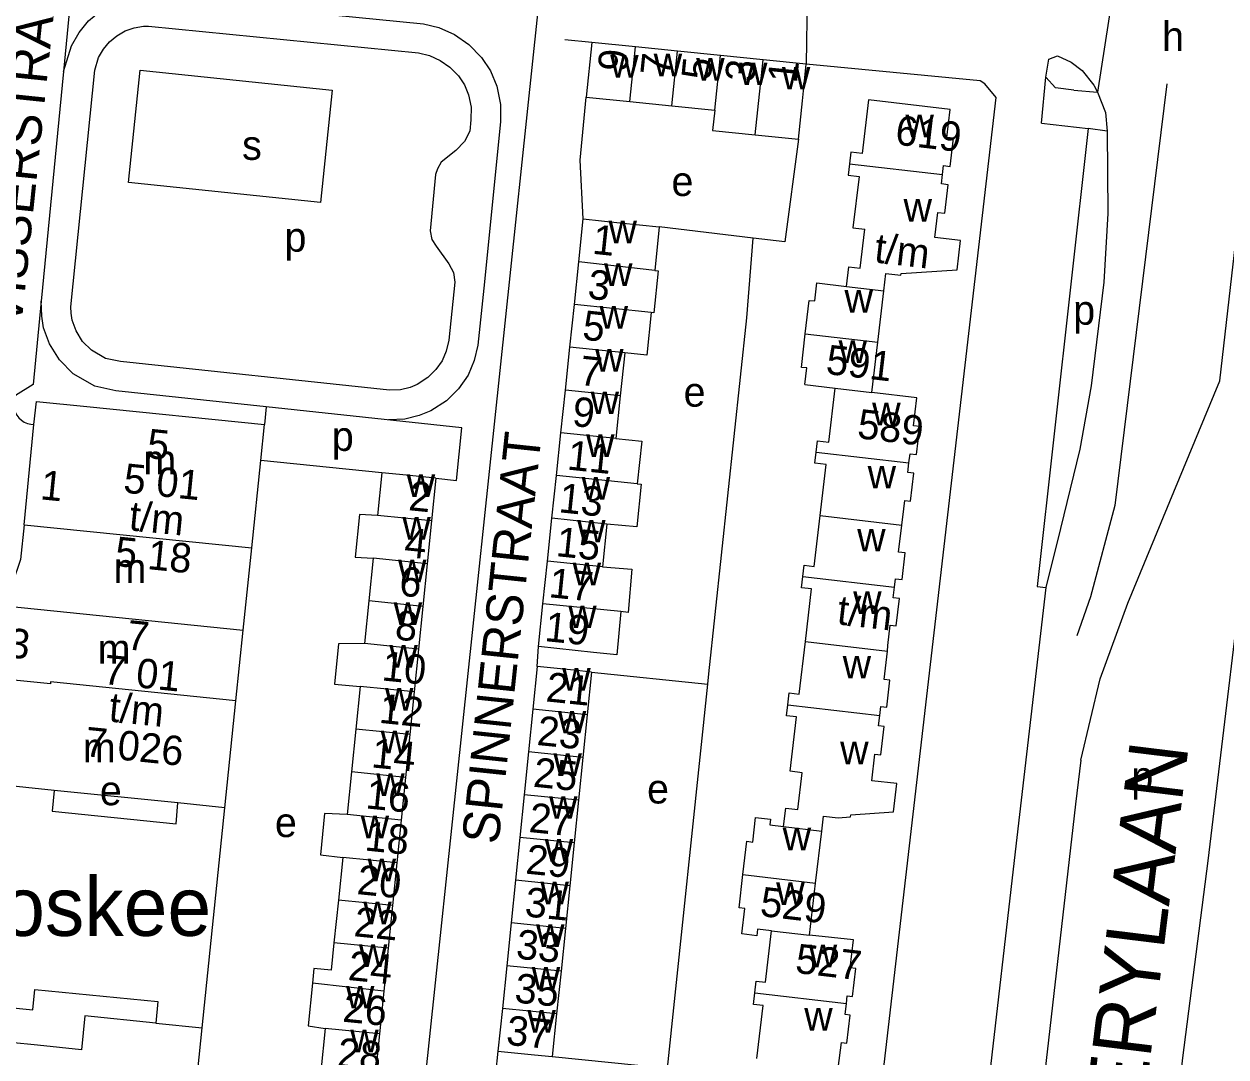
# Model space of a CAD drawing. Extents: x 159902 to 161769, y 383692 to 384875.
# Drawn here: x 161124 to 161287.3, y 384531.5 to 384671.8 of the extents above; entities that cross this region are included whole.
import ezdxf

# ---------------------------------------------------------------- set-up
doc = ezdxf.new("R2010")
doc.units = 0
for name, color, linetype in [('BLT_Basislijn', 7, 'Continuous'), ('BLT_Bebouwing', 7, 'Continuous'), ('BLT_Bebouwing_beschrifting', 7, 'Continuous'), ('BLT_Centroide', 7, 'Continuous'), ('BLT_Huisnummer', 7, 'Continuous'), ('BLT_Huisnummer_ tussenligend', 7, 'Continuous'), ('BLT_Huisnummer_reeks', 7, 'Continuous'), ('BLT_Onderverdeling_panden', 7, 'Continuous'), ('BLT_Straatnaam', 7, 'Continuous'), ('BLT_Straatnaam_hoofdweg', 7, 'Continuous'), ('BLT_Vlakafsluiter', 7, 'Continuous')]:
    doc.layers.add(name, color=color, linetype=linetype)

msp = doc.modelspace()

# ---------------------------------------------------------------- linework, layer by layer
at = {"layer": 'BLT_Basislijn'}
for p, q in [((161193.76, 384673.22), (161175.44, 384500)), ((161201.12, 384669.34), (161197.44, 384669.67)), ((161262.19, 384658.36), (161262.82, 384664.61)), ((161279.25, 384663.69), (161272.18, 384606.45)), ((161266.61, 384662.85), (161269.82, 384662.59)), ((161262.19, 384658.36), (161268.57, 384657.64)), ((161223.05, 384642.76), (161210.28, 384644.28)), ((161291.56, 384614.73), (161284.82, 384558.18)), ((161172.6, 384610.88), (161156.15, 384612.55)), ((161262.8, 384595.29), (161258.48, 384558.22)), ((161268.88, 384594.05), (161266.99, 384588.75)), ((161193.71, 384584.56), (161193.89, 384587.27)), ((161201.08, 384583.81), (161216.88, 384582.19)), ((161211.42, 384530.02), (161216.88, 384582.19)), ((161267.56, 384571.85), (161266.85, 384565.87)), ((161266.85, 384565.87), (161261.55, 384519.94)), ((161258.48, 384558.22), (161254.02, 384519.21)), ((161188.38, 384532.33), (161188.05, 384529.26)), ((161195.75, 384531.58), (161211.42, 384530.02))]:
    msp.add_line(p, q, dxfattribs=at)
for points in [[(161128.1, 384675.7), (161130.08, 384672.9), (161129.35, 384665.36)], [(161129.35, 384665.36), (161130.44, 384668.87), (161131.47, 384670.69), (161132.76, 384672.24), (161134.31, 384673.54), (161136.06, 384674.54), (161137.96, 384675.21), (161139.86, 384675.52), (161141.03, 384675.55), (161178.24, 384671.86), (161180.36, 384671.34), (161182.49, 384670.39), (161184.43, 384669.05), (161186.15, 384667.3), (161187.37, 384665.46), (161188.22, 384663.37), (161188.74, 384660.91), (161188.71, 384658.61), (161186.53, 384636.82)], [(161262.82, 384664.61), (161263.2, 384667.05), (161264.4, 384667.53), (161266.22, 384666.66), (161267.73, 384665.52), (161269.33, 384663.54), (161269.82, 384662.59)], [(161129.35, 384665.36), (161126.33, 384634.17)], [(161139.77, 384665.57), (161165.87, 384662.86), (161164.28, 384647.58), (161138.18, 384650.3), (161139.77, 384665.57)], [(161237.71, 384503.53), (161256.05, 384661.86), (161254.51, 384663.72), (161253.87, 384664.1), (161230.24, 384666.36)], [(161266.61, 384662.85), (161264.13, 384663.16), (161262.82, 384664.61)], [(161199.97, 384645.36), (161199.53, 384653.33), (161200.36, 384661.9)], [(161269.82, 384662.59), (161270.9, 384659.82), (161271.13, 384657.29)], [(161268.57, 384657.64), (161261.64, 384595.42), (161262.8, 384595.29)], [(161271.13, 384657.29), (161268.57, 384657.64)], [(161271.13, 384657.29), (161271.24, 384646.08), (161270.7, 384636.78), (161268.97, 384622.67)], [(161229.19, 384656.17), (161227.36, 384642.26), (161223.05, 384642.76)], [(161267.56, 384571.85), (161270.19, 384582.9), (161273.95, 384593.17), (161280.19, 384608.27), (161286.43, 384623.37), (161290.01, 384654.67)], [(161216.88, 384582.19), (161217.02, 384583.58), (161222.17, 384631.94), (161223.05, 384642.76)], [(161186.53, 384636.82), (161185.65, 384628.21), (161185.16, 384626.15), (161184.32, 384624.15), (161183.03, 384622.3), (161181.38, 384620.67), (161179.26, 384619.31), (161177.67, 384618.66), (161175.71, 384618.18), (161173.5, 384618.07)], [(161126.33, 384634.17), (161125.24, 384622.87), (161122.85, 384621.39)], [(161156.91, 384619.84), (161136.45, 384622.03), (161133.61, 384622.64), (161130.68, 384624.32), (161128.8, 384626.22), (161127.44, 384628.41), (161126.66, 384630.58), (161126.4, 384632.17), (161126.33, 384634.17)], [(161268.97, 384622.67), (161267.43, 384614.08), (161264.77, 384603.29), (161262.8, 384595.29)], [(161122.85, 384621.39), (161122.68, 384620.95), (161122.59, 384620.49), (161122.58, 384620.03), (161122.64, 384619.56), (161122.79, 384619.11), (161123.01, 384618.7), (161123.29, 384618.33), (161123.64, 384618.01), (161124.03, 384617.75), (161124.46, 384617.57), (161124.92, 384617.46), (161125.35, 384617.42)], [(161156.91, 384619.84), (161156.65, 384617.45)], [(161183.48, 384617), (161156.91, 384619.84)], [(161179.95, 384610.13), (161182.76, 384609.85), (161183.48, 384617)], [(161272.18, 384606.45), (161268.88, 384594.05)], [(161284.82, 384558.18), (161281.35, 384531.41), (161279.58, 384515.63)]]:
    msp.add_lwpolyline(points, dxfattribs=at)
msp.add_lwpolyline([(161140.89, 384671.55), (161177.56, 384667.91), (161179.06, 384667.54), (161180.52, 384666.89), (161181.84, 384665.97), (161183.02, 384664.77), (161183.82, 384663.57), (161184.39, 384662.19), (161184.73, 384660.52), (161184.71, 384658.82), (161184.57, 384657.26), (161183.85, 384655.87), (161182.65, 384654.65), (161180.67, 384653.05), (161180.14, 384652.18), (161179.89, 384651.38), (161179.17, 384643.72), (161179.4, 384642.56), (161179.99, 384641.64), (161181.72, 384639.24), (161182.32, 384638.08), (161182.51, 384636.75), (161181.69, 384628.87), (161181.35, 384627.4), (161180.8, 384626.1), (161179.95, 384624.89), (161178.86, 384623.81), (161177.41, 384622.87), (161176.43, 384622.48), (161175.12, 384622.15), (161173.62, 384622.08), (161137.09, 384625.99), (161135.06, 384626.42), (161133.14, 384627.52), (161131.96, 384628.71), (161131.07, 384630.15), (161130.55, 384631.6), (161130.39, 384632.57), (161130.36, 384633.4), (161133.6, 384665.55), (161134.13, 384667.28), (161134.77, 384668.41), (161135.61, 384669.41), (161136.6, 384670.24), (161137.73, 384670.89), (161138.96, 384671.32), (161140.24, 384671.53)], close=True, dxfattribs=at)
at = {"layer": 'BLT_Bebouwing'}
for p, q in [((161201.12, 384669.34), (161200.36, 384661.9)), ((161207.06, 384668.74), (161201.12, 384669.34)), ((161212.77, 384668.15), (161207.06, 384668.74)), ((161218.59, 384667.55), (161212.77, 384668.15)), ((161224.41, 384666.96), (161218.59, 384667.55)), ((161230.24, 384666.36), (161224.41, 384666.96)), ((161206.29, 384661.29), (161212.01, 384660.71)), ((161212.01, 384660.71), (161217.83, 384660.11)), ((161223.3, 384656.77), (161229.19, 384656.17)), ((161199.36, 384639.55), (161199.97, 384645.36)), ((161210.28, 384644.28), (161209.67, 384638.37)), ((161236.6, 384644.15), (161238.19, 384643.96)), ((161198.76, 384633.75), (161199.36, 384639.55)), ((161239.96, 384628.6), (161240.78, 384635.6)), ((161198.15, 384627.94), (161198.76, 384633.75)), ((161197.54, 384622.12), (161198.15, 384627.94)), ((161239.17, 384621.79), (161239.96, 384628.6)), ((161205.6, 384627.15), (161204.99, 384621.34)), ((161230.06, 384622.86), (161234.17, 384622.38)), ((161196.93, 384616.32), (161197.54, 384622.12)), ((161204.99, 384621.34), (161204.38, 384615.53)), ((161156.15, 384612.55), (161156.65, 384617.45)), ((161196.32, 384610.51), (161196.93, 384616.32)), ((161154.93, 384600.69), (161156.15, 384612.55)), ((161172.6, 384610.88), (161172.01, 384605.08)), ((161179.95, 384610.13), (161179.36, 384604.34)), ((161195.71, 384604.7), (161196.32, 384610.51)), ((161179.36, 384604.34), (161178.77, 384598.53)), ((161195.1, 384598.89), (161195.71, 384604.7)), ((161203.17, 384603.91), (161202.56, 384598.1)), ((161153.77, 384589.52), (161154.93, 384600.69)), ((161171.42, 384599.28), (161170.83, 384593.47)), ((161178.77, 384598.53), (161178.18, 384592.73)), ((161194.49, 384593.08), (161195.1, 384598.89)), ((161170.83, 384593.47), (161170.24, 384587.67)), ((161193.89, 384587.27), (161194.49, 384593.08)), ((161178.18, 384592.73), (161177.59, 384586.92)), ((161152.78, 384579.92), (161153.77, 384589.52)), ((161177.59, 384586.92), (161177, 384581.11)), ((161193.71, 384584.56), (161193.12, 384578.76)), ((161201.08, 384583.81), (161200.49, 384578.01)), ((161169.65, 384581.86), (161169.06, 384576.06)), ((161151.28, 384565.39), (161152.78, 384579.92)), ((161177, 384581.11), (161176.41, 384575.31)), ((161193.12, 384578.76), (161192.53, 384572.96)), ((161200.49, 384578.01), (161199.9, 384572.2)), ((161169.06, 384576.06), (161168.46, 384570.25)), ((161176.41, 384575.31), (161175.82, 384569.51)), ((161192.53, 384572.96), (161191.93, 384567.15)), ((161199.9, 384572.2), (161199.31, 384566.4)), ((161168.46, 384570.25), (161167.88, 384564.45)), ((161175.82, 384569.51), (161175.23, 384563.7)), ((161144.88, 384566.03), (161128.1, 384567.73)), ((161191.93, 384567.15), (161191.34, 384561.35)), ((161148.19, 384535.5), (161151.28, 384565.39)), ((161199.31, 384566.4), (161198.71, 384560.6)), ((161175.23, 384563.7), (161174.64, 384557.9)), ((161231.53, 384555.14), (161232.36, 384562.21)), ((161191.34, 384561.35), (161190.75, 384555.54)), ((161198.71, 384560.6), (161198.12, 384554.79)), ((161167.29, 384558.64), (161166.7, 384552.84)), ((161174.64, 384557.9), (161174.05, 384552.09)), ((161190.75, 384555.54), (161190.16, 384549.74)), ((161198.12, 384554.79), (161197.53, 384548.99)), ((161230.7, 384548.06), (161231.53, 384555.14)), ((161166.7, 384552.84), (161166.1, 384547.03)), ((161174.05, 384552.09), (161173.46, 384546.29)), ((161190.16, 384549.74), (161189.57, 384543.93)), ((161197.53, 384548.99), (161196.94, 384543.18)), ((161173.46, 384546.29), (161172.87, 384540.48)), ((161189.57, 384543.93), (161188.97, 384538.13)), ((161196.94, 384543.18), (161196.35, 384537.38)), ((161172.87, 384540.48), (161172.28, 384534.68)), ((161188.97, 384538.13), (161188.38, 384532.33)), ((161196.35, 384537.38), (161195.75, 384531.58)), ((161147.6, 384529.75), (161148.19, 384535.5)), ((161172.28, 384534.68), (161171.69, 384528.87))]:
    msp.add_line(p, q, dxfattribs=at)
for points in [[(161229.19, 384656.17), (161229.73, 384661.39), (161230.24, 384666.36)], [(161200.36, 384661.9), (161206.29, 384661.29)], [(161248.76, 384651.38), (161248.91, 384652.61), (161249.81, 384652.5), (161250.26, 384656.33), (161249.36, 384656.43), (161249.81, 384660.21), (161238.69, 384661.51), (161237.84, 384654.23), (161236.29, 384654.41), (161236.11, 384652.86)], [(161217.83, 384660.11), (161217.52, 384657.36), (161223.3, 384656.77)], [(161236.11, 384652.86), (161235.93, 384651.32), (161237.42, 384651.14), (161236.6, 384644.15)], [(161247.74, 384642.84), (161248.14, 384646.23), (161249.08, 384646.12), (161249.53, 384650.01), (161248.61, 384650.11), (161248.76, 384651.38)], [(161199.97, 384645.36), (161204.94, 384644.84), (161210.28, 384644.28)], [(161235.71, 384636.2), (161236.03, 384638.85), (161237.57, 384638.67), (161238.19, 384643.96)], [(161240.78, 384635.6), (161241.06, 384637.95), (161243.11, 384637.71), (161243.14, 384637.94), (161250.75, 384638.43), (161251.22, 384642.43), (161247.74, 384642.84)], [(161209.67, 384638.37), (161210.15, 384638.32), (161209.55, 384632.62), (161209.2, 384632.65)], [(161230.12, 384629.75), (161230.65, 384634.3), (161231.41, 384634.22), (161231.69, 384636.67), (161235.71, 384636.2)], [(161209.2, 384632.65), (161208.6, 384626.85), (161205.6, 384627.15)], [(161230.06, 384622.86), (161230.33, 384625.11), (161229.59, 384625.19), (161230.12, 384629.75)], [(161231.59, 384613.7), (161231.77, 384615.22), (161233.31, 384615.04), (161234.17, 384622.38)], [(161244.2, 384612.22), (161244.35, 384613.45), (161245.24, 384613.35), (161245.69, 384617.15), (161244.84, 384617.24), (161245.28, 384621.08), (161239.17, 384621.79)], [(161125.35, 384617.42), (161125.67, 384620.57)], [(161125.67, 384620.57), (161132.51, 384619.88), (161156.65, 384617.45)], [(161124, 384603.81), (161125.35, 384617.42)], [(161204.38, 384615.53), (161207.9, 384615.16), (161207.29, 384609.38)], [(161232.14, 384605.08), (161232.95, 384612), (161231.42, 384612.18), (161231.59, 384613.7)], [(161179.95, 384610.13), (161174.98, 384610.64), (161172.6, 384610.88)], [(161243.23, 384603.78), (161243.5, 384606), (161243.63, 384607.12), (161244.42, 384607.03), (161244.86, 384610.83), (161244.05, 384610.92), (161244.2, 384612.22)], [(161207.29, 384609.38), (161207.83, 384609.32), (161207.22, 384603.54), (161203.17, 384603.91)], [(161172.01, 384605.08), (161169.56, 384605.22), (161168.97, 384599.43), (161171.42, 384599.28)], [(161229.79, 384596.78), (161229.97, 384598.32), (161231.33, 384598.16), (161232.14, 384605.08)], [(161124, 384603.81), (161123.53, 384599.12), (161121.37, 384592.82)], [(161242.24, 384595.32), (161242.38, 384596.47), (161243.27, 384596.37), (161243.7, 384600), (161242.78, 384600.11), (161243.23, 384603.78)], [(161202.56, 384598.1), (161206.54, 384597.78), (161206.07, 384591.92), (161205.08, 384592.05)], [(161230.13, 384587.96), (161230.97, 384595.11), (161229.61, 384595.27), (161229.79, 384596.78)], [(161241.27, 384586.66), (161241.35, 384587.42), (161241.67, 384590.19), (161242.49, 384590.09), (161242.93, 384593.81), (161242.07, 384593.91), (161242.24, 384595.32)], [(161205.08, 384592.05), (161204.52, 384586.15), (161201.34, 384586.48), (161198.86, 384586.74), (161193.89, 384587.27)], [(161170.24, 384587.67), (161166.72, 384587.63), (161166.16, 384582.18), (161169.65, 384581.86)], [(161227.75, 384579.38), (161227.93, 384580.97), (161229.3, 384580.81), (161230.13, 384587.96)], [(161240.23, 384577.92), (161240.37, 384579.12), (161241.2, 384579.03), (161241.63, 384582.69), (161240.83, 384582.79), (161241.27, 384586.66)], [(161201.08, 384583.81), (161198.68, 384584.05), (161193.71, 384584.56)], [(161229.68, 384570.14), (161228.05, 384570.33), (161228.91, 384577.73), (161227.58, 384577.88), (161227.75, 384579.38)], [(161239.17, 384569.04), (161239.59, 384572.67), (161240.4, 384572.57), (161240.85, 384576.42), (161240.06, 384576.51), (161240.23, 384577.92)], [(161227.16, 384562.82), (161227.46, 384565.32), (161229.1, 384565.13), (161229.68, 384570.14)], [(161232.36, 384562.21), (161232.59, 384564.24), (161234.59, 384564), (161236.26, 384564.14), (161236.3, 384564.44), (161242.11, 384564.85), (161242.55, 384568.67), (161239.17, 384569.04)], [(161128.1, 384567.73), (161127.82, 384564.91), (161144.65, 384563.19), (161144.88, 384566.03)], [(161167.88, 384564.45), (161164.83, 384564.59), (161164.26, 384558.98), (161167.29, 384558.64)], [(161221.66, 384556.3), (161222.19, 384560.83), (161222.99, 384560.73), (161223.38, 384564.07), (161225.38, 384563.84), (161225.29, 384563.04), (161227.16, 384562.82)], [(161225.53, 384548.67), (161223.62, 384548.89), (161223.52, 384548), (161221.51, 384548.24), (161221.91, 384551.68), (161221.13, 384551.77), (161221.66, 384556.3)], [(161223.27, 384540.24), (161223.46, 384541.83), (161224.72, 384541.68), (161225.53, 384548.67)], [(161235.7, 384538.79), (161235.82, 384539.82), (161236.55, 384539.74), (161237, 384543.54), (161236.22, 384543.63), (161236.67, 384547.44), (161230.7, 384548.06)], [(161166.1, 384547.03), (161165.73, 384543.32), (161163.38, 384543.56), (161163.18, 384541.55)], [(161109.94, 384539.46), (161125.17, 384537.95), (161125.45, 384540.68), (161142.16, 384539.07), (161141.89, 384536.14)], [(161163.18, 384541.55), (161162.59, 384535.76), (161164.92, 384535.42)], [(161223.55, 384531.32), (161224.39, 384538.51), (161223.09, 384538.66), (161223.27, 384540.24)], [(161234.6, 384530.03), (161235.02, 384533.49), (161235.76, 384533.41), (161236.2, 384537.23), (161235.52, 384537.31), (161235.7, 384538.79)], [(161141.89, 384536.14), (161132.27, 384537.11), (161131.81, 384532.52)], [(161164.92, 384535.42), (161164.33, 384529.62), (161166.72, 384529.38), (161171.69, 384528.87)], [(161131.81, 384532.52), (161125.81, 384533.13), (161118.46, 384533.87)], [(161188.38, 384532.33), (161193.36, 384531.82), (161195.75, 384531.58)]]:
    msp.add_lwpolyline(points, dxfattribs=at)
at = {"layer": 'BLT_Onderverdeling_panden'}
for p, q in [((161206.29, 384661.29), (161207.06, 384668.74)), ((161212.01, 384660.71), (161212.77, 384668.15)), ((161217.83, 384660.11), (161218.59, 384667.55)), ((161223.3, 384656.77), (161224.41, 384666.96)), ((161236.11, 384652.86), (161248.76, 384651.38)), ((161209.67, 384638.37), (161199.36, 384639.55)), ((161235.71, 384636.2), (161240.78, 384635.6)), ((161209.2, 384632.65), (161198.76, 384633.75)), ((161230.12, 384629.75), (161239.96, 384628.6)), ((161205.6, 384627.15), (161198.15, 384627.94)), ((161234.17, 384622.38), (161239.17, 384621.79)), ((161204.99, 384621.34), (161197.54, 384622.12)), ((161204.38, 384615.53), (161196.93, 384616.32)), ((161231.59, 384613.7), (161244.2, 384612.22)), ((161207.29, 384609.38), (161196.32, 384610.51)), ((161179.36, 384604.34), (161172.01, 384605.08)), ((161203.17, 384603.91), (161195.71, 384604.7)), ((161232.14, 384605.08), (161243.23, 384603.78)), ((161124, 384603.81), (161154.93, 384600.69)), ((161178.77, 384598.53), (161171.42, 384599.28)), ((161202.56, 384598.1), (161195.1, 384598.89)), ((161229.79, 384596.78), (161242.24, 384595.32)), ((161178.18, 384592.73), (161170.83, 384593.47)), ((161205.08, 384592.05), (161194.49, 384593.08)), ((161121.37, 384592.82), (161153.77, 384589.52)), ((161177.59, 384586.92), (161170.24, 384587.67)), ((161230.13, 384587.96), (161241.27, 384586.66)), ((161177, 384581.11), (161169.65, 384581.86)), ((161200.49, 384578.01), (161193.12, 384578.76)), ((161227.75, 384579.38), (161240.23, 384577.92)), ((161176.41, 384575.31), (161169.06, 384576.06)), ((161199.9, 384572.2), (161192.53, 384572.96)), ((161175.82, 384569.51), (161168.46, 384570.25)), ((161128.1, 384567.73), (161113.26, 384569.26)), ((161199.31, 384566.4), (161191.93, 384567.15)), ((161151.28, 384565.39), (161144.88, 384566.03)), ((161175.23, 384563.7), (161167.88, 384564.45)), ((161227.16, 384562.82), (161232.36, 384562.21)), ((161198.71, 384560.6), (161191.34, 384561.35)), ((161174.64, 384557.9), (161167.29, 384558.64)), ((161198.12, 384554.79), (161190.75, 384555.54)), ((161221.66, 384556.3), (161231.53, 384555.14)), ((161174.05, 384552.09), (161166.7, 384552.84)), ((161197.53, 384548.99), (161190.16, 384549.74)), ((161225.53, 384548.67), (161230.7, 384548.06)), ((161173.46, 384546.29), (161166.1, 384547.03)), ((161196.94, 384543.18), (161189.57, 384543.93)), ((161172.87, 384540.48), (161163.18, 384541.55)), ((161223.27, 384540.24), (161235.7, 384538.79)), ((161196.35, 384537.38), (161188.97, 384538.13)), ((161141.89, 384536.14), (161148.19, 384535.5)), ((161172.28, 384534.68), (161164.92, 384535.42))]:
    msp.add_line(p, q, dxfattribs=at)
msp.add_lwpolyline([(161152.78, 384579.92), (161127.6, 384582.48), (161127.58, 384582.2), (161118.05, 384583.16)], dxfattribs=at)
at = {"layer": 'BLT_Vlakafsluiter'}
for p, q in [((161230.51, 384686.75), (161230.24, 384666.36)), ((161272.58, 384680.26), (161269.82, 384662.59))]:
    msp.add_line(p, q, dxfattribs=at)

# ---------------------------------------------------------------- texts
at = {"layer": 'BLT_Bebouwing_beschrifting'}
msp.add_text('Moskee', height=8, dxfattribs=at).set_placement((161111.97, 384547.98))
at = {"layer": 'BLT_Centroide'}
for s, p in [('h', (161278.59, 384668.16)), ('w', (161203.62, 384664.56)), ('w', (161209.53, 384664.72)), ('w', (161215.3, 384664.14)), ('w', (161221.12, 384663.53)), ('w', (161226.94, 384662.94)), ('w', (161243.73, 384656.44)), ('s', (161153.62, 384653.38)), ('e', (161211.95, 384648.47)), ('w', (161243.47, 384644.98)), ('p', (161159.38, 384640.91)), ('w', (161203.39, 384642.06)), ('w', (161202.79, 384636.25)), ('w', (161235.45, 384632.62)), ('p', (161266.52, 384630.99)), ('w', (161202.18, 384630.44)), ('w', (161234.64, 384625.78)), ('w', (161201.57, 384624.62)), ('e', (161213.6, 384619.86)), ('w', (161200.96, 384618.84)), ('w', (161239.21, 384617.31)), ('p', (161165.81, 384613.85)), ('w', (161200.35, 384613.03)), ('m', (161140.21, 384610.66)), ('w', (161238.59, 384608.75)), ('w', (161175.98, 384607.59)), ('w', (161199.74, 384607.22)), ('w', (161175.39, 384601.81)), ('w', (161199.13, 384601.41)), ('w', (161237.17, 384600.19)), ('m', (161136.16, 384595.93)), ('w', (161174.8, 384596)), ('w', (161198.52, 384595.59)), ('w', (161236.63, 384591.72)), ('w', (161174.21, 384590.19)), ('w', (161197.92, 384589.78)), ('m', (161134, 384584.97)), ('w', (161173.62, 384584.41)), ('w', (161235.2, 384582.94)), ('w', (161197.1, 384581.28)), ('w', (161173.03, 384578.59)), ('w', (161196.51, 384575.47)), ('w', (161172.44, 384572.78)), ('m', (161131.99, 384571.54)), ('w', (161234.86, 384571.28)), ('w', (161195.91, 384569.69)), ('p', (161274.42, 384567.68)), ('e', (161134.3, 384565.72)), ('w', (161171.84, 384566.97)), ('e', (161208.63, 384565.96)), ('w', (161195.32, 384563.88)), ('e', (161158.08, 384561.4)), ('w', (161169.73, 384561.25)), ('w', (161227.05, 384559.59)), ('w', (161194.73, 384558.06)), ('w', (161170.67, 384555.38)), ('w', (161194.14, 384552.25)), ('w', (161226.17, 384552.16)), ('w', (161170.08, 384549.56)), ('w', (161193.55, 384546.47)), ('w', (161169.48, 384543.75)), ('w', (161230.59, 384543.72)), ('w', (161192.96, 384540.66)), ('w', (161167.73, 384538.12)), ('w', (161192.37, 384534.84)), ('w', (161229.98, 384535.12)), ('w', (161168.31, 384532.16))]:
    msp.add_text(s, height=4, dxfattribs=at).set_placement(p)
at = {"layer": 'BLT_Huisnummer'}
for s, rotation, p in [('9', 84.153, (161205.89, 384665.25)), ('5', 84.1538, (161217.25, 384664.12)), ('1', 84.1493, (161228.98, 384663.71)), ('1', 354.0142, (161201.09, 384640.64)), ('5', 354.0218, (161199.74, 384628.98)), ('9', 354.021, (161198.35, 384617.26)), ('1', 354.2039, (161126.1, 384607.29)), ('2', 354.1938, (161176.13, 384605.81)), ('13', 354.0202, (161196.53, 384605.53)), ('6', 354.1938, (161174.85, 384594.22)), ('17', 354.1697, (161195.18, 384593.99)), ('3', 354.2039, (161121.64, 384585.84)), ('10', 354.1946, (161172.49, 384582.69)), ('21', 354.1755, (161194.78, 384579.84)), ('14', 354.1946, (161171.08, 384570.88)), ('25', 354.1832, (161193.06, 384568.25)), ('18', 354.1946, (161170.17, 384559.59)), ('29', 354.1755, (161192.04, 384556.45)), ('22', 354.1954, (161168.7, 384547.95)), ('33', 354.1755, (161190.73, 384544.91)), ('26', 354.2038, (161167.18, 384536.34)), ('37', 354.1542, (161189.39, 384533.21))]:
    msp.add_text(s, height=4, rotation=rotation, dxfattribs=at).set_placement(p)
at = {"layer": 'BLT_Huisnummer_ tussenligend'}
for s, rotation, p in [('7', 84.1538, (161211.68, 384664.68)), ('3', 84.1493, (161223.17, 384663.84)), ('3', 354.0142, (161200.45, 384634.54)), ('7', 354.0218, (161199.34, 384622.83)), ('11', 354.021, (161197.67, 384611.33)), ('4', 354.1938, (161175.54, 384599.47)), ('15', 354.0202, (161196.15, 384599.57)), ('8', 354.1938, (161174.28, 384588.26)), ('19', 354.1697, (161194.62, 384588.03)), ('12', 354.1946, (161172.12, 384576.93)), ('23', 354.1755, (161193.56, 384573.92)), ('16', 354.1946, (161170.31, 384565.31)), ('27', 354.1832, (161192.47, 384562.1)), ('20', 354.1946, (161169.11, 384553.67)), ('31', 354.1755, (161191.91, 384550.64)), ('24', 354.1954, (161167.91, 384542)), ('35', 354.1755, (161190.53, 384538.95)), ('28', 354.2038, (161166.42, 384530.19))]:
    msp.add_text(s, height=4, rotation=rotation, dxfattribs=at).set_placement(p)
at = {"layer": 'BLT_Huisnummer_reeks'}
for s, rotation, p in [('619', 353.3224, (161242.22, 384655.48)), ('t/m', 353.3249, (161239.39, 384639.47)), ('591', 353.3333, (161232.81, 384624.32)), ('589', 353.3234, (161237.07, 384615.59)), ('5', 354.2039, (161140.56, 384612.9)), ('5 01', 354.2039, (161137.39, 384608.2)), ('t/m', 354.2039, (161138.15, 384603.09)), ('5 18', 354.2039, (161136.21, 384598.26)), ('t/m', 353.3302, (161234.33, 384590.31)), ('7', 354.2039, (161137.81, 384586.91)), ('7 01', 354.2039, (161134.65, 384582.21)), ('t/m', 354.2039, (161135.41, 384577.11)), ('7 026', 354.2039, (161132.13, 384572.41)), ('529', 353.3326, (161223.86, 384550.7)), ('527', 353.3284, (161228.65, 384542.97))]:
    msp.add_text(s, height=4, rotation=rotation, dxfattribs=at).set_placement(p)
at = {"layer": 'BLT_Straatnaam'}
for s, rotation, p in [('VISSERSTRAAT', 84.0538, (161123.62, 384630.68)), ('SPINNERSTRAAT', 83.9872, (161188.44, 384560.32)), ('VISSERSTRAAT', 303.0305, (161093.24, 384541.84))]:
    msp.add_text(s, height=5, rotation=rotation, dxfattribs=at).set_placement(p)
at = {"layer": 'BLT_Straatnaam_hoofdweg'}
msp.add_text('VELDMAARSCHALK MONTGOMERYLAAN', height=8, rotation=82.9908, dxfattribs=at).set_placement((161256.38, 384363.69))

doc.saveas('drawing.dxf')
